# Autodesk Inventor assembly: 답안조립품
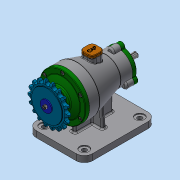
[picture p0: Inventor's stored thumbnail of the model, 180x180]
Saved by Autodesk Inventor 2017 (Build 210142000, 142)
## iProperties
Part Number: 답안조립품
Material: 일반
Document SubType Name: Assembly
Designer: user
Author: user
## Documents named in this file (16)
- C:\Users\user\Desktop\711006V1002\답안조립품.iam
- C:\Users\user\Desktop\711006V1002\1.본체.ipt
- C:\Users\user\Desktop\711006V1002\앞커버.ipt
- C:\Users\user\Desktop\711006V1002\뒤커버.ipt
- C:\Users\user\Desktop\711006V1002\베어링 6200.ipt
- C:\Users\user\Desktop\711006V1002\베어링 6203.ipt
- C:\Users\user\Desktop\711006V1002\축.ipt
- C:\Users\user\Desktop\711006V1002\키 5x5.ipt
- 키 5 x 5.ipt
- C:\Users\user\Desktop\711006V1002\오일 실 17x30x8.ipt
- C:\Users\user\Desktop\711006V1002\오일 실 10x20x7.ipt
- C:\Users\user\Desktop\711006V1002\볼트 M4.ipt
- 볼트 M4 x 12.ipt
- C:\Users\user\Desktop\711006V1002\마개.ipt
- C:\Users\user\Desktop\711006V1002\스프로킷.ipt
- C:\Users\user\Desktop\711006V1002\와셔.ipt
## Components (1 placed, 1 different names)
1. 1.본체:1
